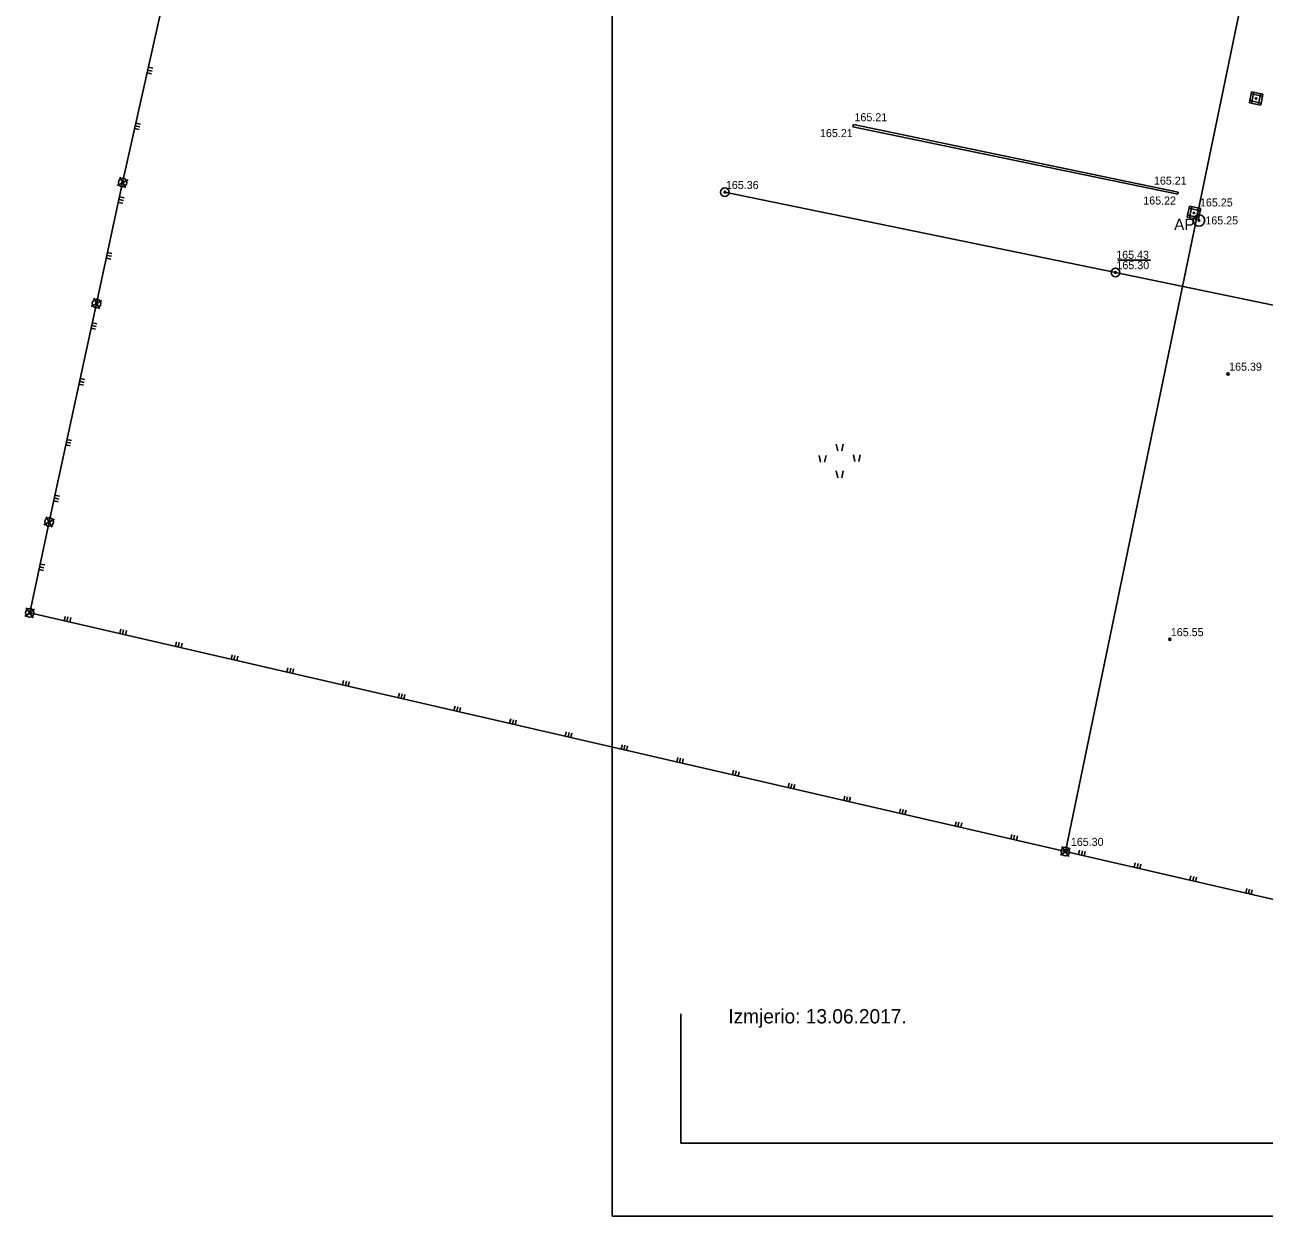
# Model space of a CAD drawing. Extents: x 492698 to 492905, y 5129124 to 5129334.
# Drawn here: x 492697.5 to 492805.9, y 5129123.7 to 5129228 of the extents above; entities that cross this region are included whole.
import ezdxf

# ---------------------------------------------------------------- set-up
doc = ezdxf.new("R2010")
doc.units = 0
for name, color, linetype in [('DETALJNE TOČKE', 7, 'Continuous'), ('FRONTOVI', 7, 'Continuous'), ('MEĐA - stara', 7, 'Continuous'), ('MEĐAŠI', 7, 'Continuous'), ('OBJEKTI - novi', 7, 'Continuous'), ('OBRAZCI', 7, 'Continuous'), ('TOPO - Znakovi', 7, 'Continuous'), ('VISINE', 7, 'Continuous')]:
    doc.layers.add(name, color=color, linetype=linetype)

msp = doc.modelspace()

# ---------------------------------------------------------------- linework, layer by layer
at = {"layer": 'FRONTOVI'}
for p, q in [((492706.54, 5129214.41), (492705.6, 5129213.91)), ((492705.82, 5129214.63), (492706.32, 5129213.69)), ((492704.26, 5129203.83), (492703.32, 5129203.33)), ((492703.54, 5129204.05), (492704.04, 5129203.11)), ((492700.1, 5129184.72), (492699.18, 5129184.2)), ((492699.38, 5129184.92), (492699.9, 5129184)), ((492698.37, 5129176.82), (492697.51, 5129176.2)), ((492698.25, 5129176.08), (492697.63, 5129176.94))]:
    msp.add_line(p, q, dxfattribs=at)
for centre in [(492706.07, 5129214.16), (492703.79, 5129203.58), (492699.64, 5129184.46), (492697.94, 5129176.51)]:
    msp.add_circle(centre, 0.075, dxfattribs=at)
for centre, start, end in [((492706.07, 5129214.16), 163.5423, 343.5423), ((492706.07, 5129214.16), 343.5423, 163.5423), ((492703.79, 5129203.58), 162.6011, 342.6011), ((492703.79, 5129203.58), 342.6011, 162.6011), ((492699.64, 5129184.46), 163.8285, 343.8285), ((492699.64, 5129184.46), 343.8285, 163.8285), ((492697.94, 5129176.51), 80.7804, 260.7804), ((492697.94, 5129176.51), 260.7804, 80.7804)]:
    msp.add_arc(centre, 0.075, start, end, dxfattribs=at)
at = {"layer": 'MEĐA - stara'}
for p, q in [((492817.66, 5129296.12), (492788.55, 5129155.62)), ((492712.06, 5129241.02), (492706.07, 5129214.16)), ((492770.01, 5129219.25), (492769.95, 5129219.05)), ((492769.95, 5129219.05), (492798.38, 5129213.14)), ((492798.43, 5129213.33), (492770.01, 5129219.25)), ((492706.07, 5129214.16), (492703.79, 5129203.58)), ((492758.76, 5129213.32), (492792.93, 5129206.3)), ((492798.38, 5129213.14), (492798.43, 5129213.33)), ((492792.93, 5129206.3), (492827.24, 5129199.15)), ((492703.79, 5129203.58), (492699.64, 5129184.46)), ((492768.51, 5129191.28), (492768.63, 5129190.68)), ((492769.11, 5129191.28), (492768.98, 5129190.68)), ((492767.01, 5129190.28), (492767.13, 5129189.68)), ((492767.61, 5129190.28), (492767.48, 5129189.68)), ((492770.01, 5129190.35), (492770.13, 5129189.75)), ((492770.61, 5129190.35), (492770.48, 5129189.75)), ((492768.51, 5129188.93), (492768.63, 5129188.33)), ((492769.11, 5129188.93), (492768.98, 5129188.33)), ((492699.64, 5129184.46), (492697.94, 5129176.51)), ((492697.94, 5129176.51), (492788.55, 5129155.62)), ((492788.55, 5129155.62), (492870.12, 5129136.86))]:
    msp.add_line(p, q, dxfattribs=at)
at = {"layer": 'MEĐAŠI'}
for p, q in [((492788.98, 5129155.93), (492788.12, 5129155.31)), ((492788.24, 5129156.05), (492788.86, 5129155.19))]:
    msp.add_line(p, q, dxfattribs=at)
for centre, radius in [((492706.07, 5129214.16), 0.375), ((492758.76, 5129213.32), 0.375), ((492758.76, 5129213.32), 0.075), ((492792.93, 5129206.3), 0.375), ((492792.93, 5129206.3), 0.075), ((492703.79, 5129203.58), 0.375), ((492699.64, 5129184.46), 0.375), ((492697.94, 5129176.51), 0.375), ((492788.55, 5129155.62), 0.075)]:
    msp.add_circle(centre, radius, dxfattribs=at)
for start, end in [(170.2518, 350.2518), (350.2518, 170.2518)]:
    msp.add_arc((492788.55, 5129155.62), 0.075, start, end, dxfattribs=at)
at = {"layer": 'OBJEKTI - novi'}
msp.add_circle((492788.55, 5129155.62), 0.375, dxfattribs=at)
at = {"layer": 'OBRAZCI'}
for p, q in [((492748.91, 5129333.71), (492748.91, 5129123.71)), ((492748.91, 5129185.21), (492748.91, 5129191.21)), ((492754.91, 5129141.43), (492754.91, 5129130.09)), ((492754.91, 5129130.09), (492891.41, 5129130.09)), ((492897.41, 5129123.71), (492748.91, 5129123.71))]:
    msp.add_line(p, q, dxfattribs=at)
at = {"layer": 'TOPO - Znakovi'}
for p, q in [((492708.71, 5129224.16), (492708.32, 5129224.25)), ((492708.6, 5129223.68), (492708.21, 5129223.76)), ((492708.66, 5129223.92), (492708.27, 5129224.01)), ((492804.81, 5129221.92), (492804.69, 5129221.33)), ((492804.85, 5129222.11), (492804.81, 5129221.92)), ((492805.79, 5129221.71), (492804.81, 5129221.92)), ((492805.05, 5129222.07), (492804.84, 5129221.09)), ((492805.83, 5129221.91), (492804.85, 5129222.11)), ((492805.43, 5129220.97), (492805.64, 5129221.95)), ((492805.79, 5129221.71), (492805.83, 5129221.91)), ((492804.69, 5129221.33), (492804.65, 5129221.13)), ((492804.65, 5129221.13), (492805.63, 5129220.93)), ((492805.67, 5129221.12), (492804.69, 5129221.33)), ((492805.63, 5129220.93), (492805.67, 5129221.12)), ((492805.67, 5129221.12), (492805.79, 5129221.71)), ((492707.51, 5129218.8), (492707.12, 5129218.88)), ((492707.57, 5129219.04), (492707.18, 5129219.13)), ((492707.62, 5129219.28), (492707.23, 5129219.37)), ((492706.09, 5129212.35), (492705.7, 5129212.43)), ((492706.14, 5129212.59), (492705.75, 5129212.68)), ((492706.19, 5129212.84), (492705.8, 5129212.92)), ((492799.41, 5129212.1), (492799.37, 5129211.91)), ((492800.39, 5129211.9), (492799.41, 5129212.1)), ((492799.25, 5129211.32), (492799.21, 5129211.12)), ((492799.21, 5129211.12), (492800.19, 5129210.92)), ((492799.37, 5129211.91), (492799.25, 5129211.32)), ((492800.23, 5129211.11), (492799.25, 5129211.32)), ((492800.35, 5129211.7), (492799.37, 5129211.91)), ((492799.61, 5129212.06), (492799.4, 5129211.08)), ((492799.99, 5129210.96), (492800.2, 5129211.94)), ((492800.19, 5129210.92), (492800.23, 5129211.11)), ((492800.23, 5129211.11), (492800.35, 5129211.7)), ((492800.35, 5129211.7), (492800.39, 5129211.9)), ((492705.09, 5129207.71), (492704.7, 5129207.79)), ((492705.14, 5129207.95), (492704.75, 5129208.03)), ((492705.04, 5129207.46), (492704.64, 5129207.55)), ((492703.71, 5129201.32), (492703.32, 5129201.41)), ((492703.76, 5129201.57), (492703.37, 5129201.65)), ((492703.82, 5129201.81), (492703.42, 5129201.9)), ((492702.76, 5129196.93), (492702.36, 5129197.01)), ((492702.65, 5129196.44), (492702.26, 5129196.52)), ((492702.7, 5129196.68), (492702.31, 5129196.77)), ((492701.6, 5129191.6), (492701.21, 5129191.69)), ((492701.49, 5129191.11), (492701.1, 5129191.2)), ((492701.55, 5129191.36), (492701.16, 5129191.44)), ((492700.43, 5129186.23), (492700.04, 5129186.31)), ((492700.49, 5129186.47), (492700.09, 5129186.56)), ((492700.54, 5129186.72), (492700.15, 5129186.8)), ((492699.25, 5129180.7), (492698.85, 5129180.78)), ((492699.14, 5129180.21), (492698.75, 5129180.3)), ((492699.19, 5129180.46), (492698.8, 5129180.54)), ((492701.04, 5129176.2), (492700.95, 5129175.82)), ((492701.29, 5129176.15), (492701.2, 5129175.76)), ((492701.53, 5129176.09), (492701.44, 5129175.7)), ((492705.92, 5129175.08), (492705.83, 5129174.69)), ((492706.16, 5129175.03), (492706.07, 5129174.64)), ((492706.4, 5129174.97), (492706.31, 5129174.58)), ((492710.79, 5129173.96), (492710.7, 5129173.57)), ((492711.03, 5129173.9), (492710.94, 5129173.51)), ((492711.28, 5129173.85), (492711.19, 5129173.46)), ((492715.66, 5129172.84), (492715.57, 5129172.45)), ((492715.9, 5129172.78), (492715.81, 5129172.39)), ((492716.15, 5129172.72), (492716.06, 5129172.33)), ((492720.53, 5129171.71), (492720.44, 5129171.32)), ((492720.78, 5129171.66), (492720.69, 5129171.27)), ((492721.02, 5129171.6), (492720.93, 5129171.21)), ((492725.4, 5129170.59), (492725.31, 5129170.2)), ((492725.65, 5129170.53), (492725.56, 5129170.14)), ((492725.89, 5129170.48), (492725.8, 5129170.09)), ((492730.28, 5129169.47), (492730.19, 5129169.08)), ((492730.52, 5129169.41), (492730.43, 5129169.02)), ((492730.76, 5129169.35), (492730.67, 5129168.96)), ((492735.15, 5129168.34), (492735.06, 5129167.95)), ((492735.39, 5129168.29), (492735.3, 5129167.9)), ((492735.64, 5129168.23), (492735.55, 5129167.84)), ((492740.02, 5129167.22), (492739.93, 5129166.83)), ((492740.26, 5129167.16), (492740.17, 5129166.77)), ((492740.51, 5129167.11), (492740.42, 5129166.72)), ((492744.89, 5129166.1), (492744.8, 5129165.71)), ((492745.14, 5129166.04), (492745.05, 5129165.65)), ((492745.38, 5129165.98), (492745.29, 5129165.59)), ((492749.77, 5129164.97), (492749.68, 5129164.58)), ((492750.01, 5129164.92), (492749.92, 5129164.53)), ((492750.25, 5129164.86), (492750.16, 5129164.47)), ((492754.64, 5129163.85), (492754.55, 5129163.46)), ((492754.88, 5129163.79), (492754.79, 5129163.4)), ((492755.12, 5129163.74), (492755.04, 5129163.35)), ((492759.51, 5129162.73), (492759.42, 5129162.34)), ((492759.75, 5129162.67), (492759.66, 5129162.28)), ((492760, 5129162.61), (492759.91, 5129162.22)), ((492764.38, 5129161.6), (492764.29, 5129161.21)), ((492764.63, 5129161.55), (492764.54, 5129161.16)), ((492764.87, 5129161.49), (492764.78, 5129161.1)), ((492769.25, 5129160.48), (492769.16, 5129160.09)), ((492769.5, 5129160.42), (492769.41, 5129160.03)), ((492769.74, 5129160.37), (492769.65, 5129159.98)), ((492774.13, 5129159.36), (492774.04, 5129158.97)), ((492774.37, 5129159.3), (492774.28, 5129158.91)), ((492774.61, 5129159.24), (492774.52, 5129158.85)), ((492779, 5129158.23), (492778.91, 5129157.84)), ((492779.24, 5129158.18), (492779.15, 5129157.79)), ((492779.49, 5129158.12), (492779.4, 5129157.73)), ((492783.87, 5129157.11), (492783.78, 5129156.72)), ((492784.11, 5129157.05), (492784.02, 5129156.66)), ((492784.36, 5129157), (492784.27, 5129156.61)), ((492789.8, 5129155.74), (492789.71, 5129155.35)), ((492790.04, 5129155.69), (492789.95, 5129155.3)), ((492790.29, 5129155.63), (492790.2, 5129155.24)), ((492794.67, 5129154.62), (492794.58, 5129154.23)), ((492794.92, 5129154.57), (492794.83, 5129154.18)), ((492795.16, 5129154.51), (492795.07, 5129154.12)), ((492799.54, 5129153.5), (492799.45, 5129153.11)), ((492799.79, 5129153.45), (492799.7, 5129153.06)), ((492800.03, 5129153.39), (492799.94, 5129153)), ((492804.42, 5129152.38), (492804.33, 5129151.99)), ((492804.66, 5129152.33), (492804.57, 5129151.94)), ((492804.9, 5129152.27), (492804.81, 5129151.88))]:
    msp.add_line(p, q, dxfattribs=at)
for centre, radius in [((492805.24, 5129221.52), 0.065), ((492799.8, 5129211.51), 0.065), ((492800.24, 5129210.85), 0.5), ((492800.24, 5129210.85), 0.075)]:
    msp.add_circle(centre, radius, dxfattribs=at)
at = {"layer": 'VISINE'}
msp.add_line((492793.13, 5129207.37), (492795.99, 5129207.37), dxfattribs=at)
for centre in [(492802.79, 5129197.42), (492797.69, 5129174.19)]:
    msp.add_circle(centre, 0.1, dxfattribs=at)

# ---------------------------------------------------------------- texts
at = {"layer": 'DETALJNE TOČKE'}
msp.add_text('AP', height=1, dxfattribs=at).set_placement((492798.07, 5129210))
at = {"layer": 'OBRAZCI'}
msp.add_text('Izmjerio: 13.06.2017.', height=1.25, dxfattribs=at).set_placement((492759.06, 5129140.58))
at = {"layer": 'VISINE'}
for s, p in [('165.21', (492770.1, 5129219.53)), ('165.21', (492767.08, 5129218.14)), ('165.36', (492758.85, 5129213.6)), ('165.21', (492796.3, 5129213.98)), ('165.22', (492795.37, 5129212.24)), ('165.25', (492800.33, 5129212.07)), ('165.25', (492800.8, 5129210.5)), ('165.43', (492793, 5129207.49)), ('165.30', (492793.02, 5129206.58)), ('165.39', (492802.88, 5129197.7)), ('165.55', (492797.78, 5129174.47)), ('165.30', (492789.03, 5129156.12))]:
    msp.add_text(s, height=0.7, dxfattribs=at).set_placement(p)

doc.saveas('drawing.dxf')
